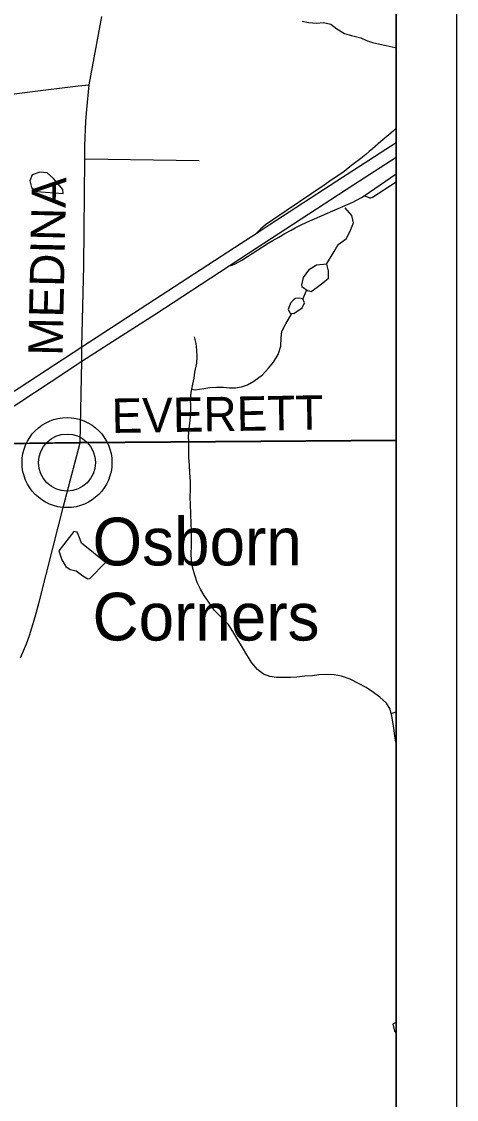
# Model space of a CAD drawing. Extents: x 0 to 34, y 0 to 22.
# Drawn here: x 8.28 to 9, y 18.033 to 19.815 of the extents above; entities that cross this region are included whole.
import ezdxf

# ---------------------------------------------------------------- set-up
doc = ezdxf.new("R2010")
doc.units = 0
for name, color, linetype in [('GM_X_Corporation', 7, 'Continuous'), ('GM_X_County_Road', 7, 'Continuous'), ('GM_X_County_Road_Text', 7, 'Continuous'), ('GM_X_Interchange_Ramps', 7, 'Continuous'), ('GM_X_Interstate_Route', 7, 'Continuous'), ('GM_X_Minor_Lake', 7, 'Continuous'), ('GM_X_Minor_River', 7, 'Continuous'), ('GM_X_Township_Road', 7, 'Continuous'), ('GM_X_Unincorporated', 7, 'Continuous'), ('GM_X_Unincorporated_Location', 7, 'Continuous'), ('GM_X_Unincorporated_Text', 7, 'Continuous'), ('SH_Data', 7, 'Continuous')]:
    doc.layers.add(name, color=color, linetype=linetype)

msp = doc.modelspace()

# ---------------------------------------------------------------- linework, layer by layer
at = {"layer": 'GM_X_Corporation'}
for points in [[(8.9, 14.1), (8.9, 20.9), (7.9922, 20.9), (7.9906, 20.6512), (7.9904, 20.2824), (7.9901, 19.6615), (7.9898, 19.1149), (7.9884, 19.0254), (7.988, 19.001), (7.9901, 18.1613), (7.991, 17.7727)], [(8.9, 14.5547), (8.9, 19.1229), (8.3772, 19.1188), (8.1678, 19.1165), (8.1319, 19.1166), (7.9898, 19.1149), (7.9884, 19.0254), (7.988, 19.001), (7.9901, 18.1613), (7.991, 17.7727)]]:
    msp.add_lwpolyline(points, dxfattribs=at)
msp.add_lwpolyline([(8.9, 19.1229), (8.9, 20.9), (7.9922, 20.9), (7.9906, 20.6512), (7.9904, 20.2824), (7.9901, 19.6615), (7.9898, 19.1149), (8.1319, 19.1166), (8.1678, 19.1165), (8.3772, 19.1188)], close=True, dxfattribs=at)
at = {"layer": 'GM_X_County_Road'}
for p, q in [((8.23, 19.1167), (8.3774, 19.1183)), ((8.3774, 19.1183), (8.9, 19.1223))]:
    msp.add_line(p, q, dxfattribs=at)
for points in [[(8.3774, 19.1183), (8.3801, 19.2537), (8.3802, 19.2774), (8.3831, 19.411), (8.3848, 19.5882), (8.3852, 19.6097), (8.3868, 19.6505), (8.3881, 19.6697), (8.3924, 19.7104), (8.4132, 19.8235)], [(8.2788, 18.7629), (8.2886, 18.7859), (8.2936, 18.8001), (8.3028, 18.8309), (8.3092, 18.8552), (8.3318, 18.9444), (8.3499, 19.0136), (8.3774, 19.1183)]]:
    msp.add_lwpolyline(points, dxfattribs=at)
at = {"layer": 'GM_X_Interchange_Ramps'}
for points in [[(8.9, 19.6387), (8.8995, 19.6381), (8.895, 19.6338), (8.8881, 19.6278), (8.8751, 19.6165), (8.8609, 19.6045), (8.8558, 19.6003), (8.8499, 19.5955), (8.8392, 19.5865), (8.8269, 19.5775), (8.8141, 19.5674), (8.8035, 19.56), (8.7926, 19.5528), (8.7811, 19.5446), (8.6978, 19.4881), (8.6841, 19.4788), (8.6758, 19.472), (8.6684, 19.4646)], [(8.6237, 19.4111), (8.6286, 19.4121), (8.634, 19.4143), (8.6449, 19.4204), (8.6886, 19.4486), (8.6951, 19.4523), (8.706, 19.4586), (8.7161, 19.4645), (8.7266, 19.4703), (8.733, 19.4739), (8.7418, 19.4782), (8.7525, 19.4832), (8.8209, 19.5131), (8.8283, 19.5166), (8.8358, 19.5202), (8.843, 19.5244), (8.8473, 19.527), (8.9, 19.5632)], [(8.8473, 19.527), (8.8497, 19.5262), (8.8529, 19.5251), (8.8562, 19.5235), (8.8584, 19.5236), (8.8609, 19.5249), (8.9, 19.55)]]:
    msp.add_lwpolyline(points, dxfattribs=at)
at = {"layer": 'GM_X_Interstate_Route'}
for points in [[(7.9952, 19.0274), (8.0811, 19.0821), (8.1321, 19.1161), (8.1684, 19.1403), (8.2762, 19.2093), (8.3802, 19.2774), (8.4893, 19.3482), (8.6437, 19.4485), (8.6684, 19.4646), (8.6899, 19.4787), (8.8022, 19.5518), (8.9, 19.6152)], [(8.4462, 19.2959), (8.5006, 19.3306), (8.6237, 19.4111), (8.6556, 19.4319), (8.8304, 19.5455), (8.9, 19.5909)], [(8.3292, 19.2201), (8.3801, 19.2537), (8.4462, 19.2959)], [(8.0881, 19.0622), (8.168, 19.116), (8.2758, 19.1849), (8.3292, 19.2201)]]:
    msp.add_lwpolyline(points, dxfattribs=at)
at = {"layer": 'GM_X_Minor_Lake'}
for points in [[(8.349, 19.5308), (8.3486, 19.5372), (8.3332, 19.5553), (8.3225, 19.5647), (8.3103, 19.5661), (8.2979, 19.5618), (8.2938, 19.5515), (8.2969, 19.5405), (8.3054, 19.534)], [(8.3054, 19.534), (8.349, 19.5308)], [(8.7534, 19.3701), (8.7595, 19.3686), (8.7693, 19.3759), (8.7788, 19.3828), (8.7885, 19.3909), (8.7884, 19.4031), (8.7857, 19.4141), (8.7686, 19.412), (8.7554, 19.4039), (8.7464, 19.392)], [(8.7464, 19.392), (8.7435, 19.38), (8.744, 19.377), (8.7534, 19.3701)], [(8.7255, 19.3497), (8.7215, 19.339), (8.7246, 19.3329), (8.731, 19.3322), (8.7446, 19.3419), (8.7483, 19.3499), (8.746, 19.3567)], [(8.746, 19.3567), (8.7402, 19.3575), (8.7339, 19.3571), (8.7305, 19.3549), (8.7255, 19.3497)], [(8.3796, 18.9528), (8.3757, 18.963), (8.3723, 18.9706), (8.3669, 18.9717), (8.3422, 18.9399), (8.3472, 18.9248), (8.3534, 18.9138), (8.361, 18.9089), (8.3706, 18.9068), (8.3816, 18.8985), (8.39, 18.8936), (8.3934, 18.8941), (8.419, 18.9205)], [(8.419, 18.9205), (8.3796, 18.9528)], [(8.9, 18.1599), (8.8946, 18.1572), (8.8977, 18.1454), (8.9, 18.1429)]]:
    msp.add_lwpolyline(points, dxfattribs=at)
at = {"layer": 'GM_X_Minor_River'}
msp.add_line((8.892, 18.6708), (8.9, 18.6737), dxfattribs=at)
for points in [[(8.7449, 19.8157), (8.7551, 19.8135), (8.7684, 19.8125), (8.7798, 19.8137), (8.792, 19.8108), (8.8023, 19.8029), (8.8149, 19.7954), (8.8263, 19.7921), (8.8419, 19.7881), (8.8514, 19.784), (8.8609, 19.7807), (8.8731, 19.7777), (8.8837, 19.7756), (8.8986, 19.7723), (8.9, 19.7721)], [(8.7851, 19.414), (8.7976, 19.4347), (8.8044, 19.4465), (8.8176, 19.4558), (8.8235, 19.4676), (8.8295, 19.4821), (8.8271, 19.4946), (8.816, 19.5071)], [(8.7519, 19.3712), (8.746, 19.3567)], [(8.562, 19.2072), (8.5678, 19.2061), (8.5822, 19.2085), (8.5921, 19.2101), (8.6027, 19.2106), (8.6145, 19.2103), (8.6243, 19.2097), (8.6346, 19.2094), (8.6444, 19.211), (8.6543, 19.2145), (8.6645, 19.2203), (8.6792, 19.2307), (8.6889, 19.2422), (8.6972, 19.2521), (8.7047, 19.2647), (8.7091, 19.2785), (8.7101, 19.2922), (8.7108, 19.3028), (8.7179, 19.3154), (8.7274, 19.3326)], [(8.9, 18.6226), (8.8998, 18.6238), (8.8982, 18.6332), (8.897, 18.6427), (8.8954, 18.6541), (8.893, 18.6666), (8.8902, 18.678), (8.8844, 18.6878), (8.873, 18.698), (8.8626, 18.7058), (8.8504, 18.7141), (8.8378, 18.7208), (8.8241, 18.7275), (8.81, 18.7327), (8.7975, 18.7349), (8.7846, 18.7355), (8.7725, 18.7346), (8.7618, 18.7334), (8.7489, 18.7325), (8.7361, 18.7312), (8.7254, 18.7304), (8.7023, 18.7302), (8.6909, 18.732), (8.6806, 18.736), (8.671, 18.7439), (8.6615, 18.7549), (8.653, 18.7681), (8.6457, 18.7798), (8.6384, 18.7926), (8.6314, 18.804), (8.6226, 18.8179), (8.6118, 18.8289), (8.5996, 18.8413), (8.59, 18.8552), (8.5827, 18.8662), (8.5765, 18.8764), (8.5707, 18.8874), (8.5668, 18.8999), (8.5633, 18.9131), (8.5616, 18.9245), (8.5612, 18.9351), (8.5614, 18.9481), (8.5617, 18.9625), (8.5616, 18.972), (8.5611, 18.9853), (8.5606, 19.0005), (8.5597, 19.0172), (8.5592, 19.0282), (8.5598, 19.0411), (8.5601, 19.0548), (8.5588, 19.0689), (8.558, 19.0818), (8.5571, 19.0943), (8.5569, 19.1197), (8.5564, 19.1292), (8.5574, 19.1414), (8.5585, 19.1509), (8.5602, 19.1657), (8.5605, 19.1798), (8.56, 19.1901), (8.561, 19.2018), (8.5636, 19.2155), (8.5658, 19.2254), (8.5672, 19.2353), (8.5701, 19.2502), (8.5711, 19.2608), (8.5703, 19.2715), (8.569, 19.2825), (8.5667, 19.2938)]]:
    msp.add_lwpolyline(points, dxfattribs=at)
at = {"layer": 'GM_X_Township_Road'}
msp.add_line((8.3848, 19.5882), (8.5743, 19.5855), dxfattribs=at)
msp.add_lwpolyline([(7.9973, 19.6608), (8.0563, 19.67), (8.1059, 19.6769), (8.1696, 19.6839), (8.234, 19.6913), (8.2938, 19.6989), (8.3739, 19.7088), (8.3924, 19.7104)], dxfattribs=at)
at = {"layer": 'GM_X_Unincorporated'}
for radius in [0.0744, 0.0472]:
    msp.add_circle((8.3555, 19.0858), radius, dxfattribs=at)
at = {"layer": 'GM_X_Unincorporated_Location'}
msp.add_line((8.3555, 19.0858), (8.3555, 19.0858), dxfattribs=at)
at = {"layer": 'SH_Data'}
for p, q in [((9, 21), (9, 14)), ((8.9, 20.9), (8.9, 14.1))]:
    msp.add_line(p, q, dxfattribs=at)

# ---------------------------------------------------------------- texts
at = {"layer": 'GM_X_County_Road_Text'}
for s, rotation, p in [('MEDINA', 88.7925, (8.3481, 19.262)), ('EVERETT', 0.9291, (8.4298, 19.1348))]:
    msp.add_text(s, height=0.05682, rotation=rotation, dxfattribs=at).set_placement(p)
at = {"layer": 'GM_X_Unincorporated_Text'}
for s, p in [('Osborn', (8.3977, 18.9158)), ('Corners', (8.3977, 18.7916))]:
    msp.add_text(s, height=0.07898, rotation=0, dxfattribs=at).set_placement(p)

doc.saveas('drawing.dxf')
